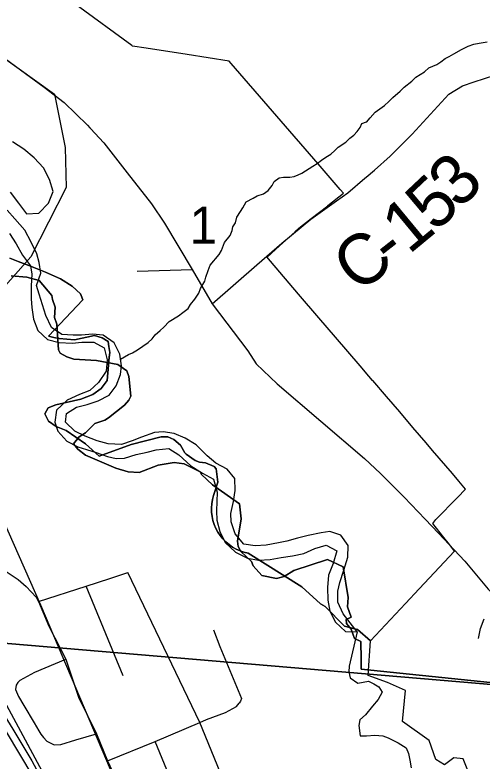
# Model space of a CAD drawing. Extents: x 0 to 43.4, y -8.1 to 22.
# Drawn here: x 3.073 to 3.6, y 17.64 to 18.481 of the extents above; entities that cross this region are included whole.
import ezdxf

# ---------------------------------------------------------------- set-up
doc = ezdxf.new("R2010")
doc.units = 0
for name, color, linetype in [('GM_X_City_Street', 7, 'Continuous'), ('GM_X_Corporation', 7, 'Continuous'), ('GM_X_County_Road', 7, 'Continuous'), ('GM_X_County_Road_Text', 7, 'Continuous'), ('GM_X_Minor_River', 7, 'Continuous'), ('GM_X_Rail_Line', 7, 'Continuous'), ('GM_X_Section_Text', 7, 'Continuous'), ('GM_X_US_Route', 7, 'Continuous')]:
    doc.layers.add(name, color=color, linetype=linetype)

msp = doc.modelspace()

# ---------------------------------------------------------------- linework, layer by layer
at = {"layer": 'GM_X_City_Street'}
for p, q in [((3.2111, 18.1925), (3.27309, 18.19442)), ((3.19527, 17.73658), (3.1535, 17.83752))]:
    msp.add_line(p, q, dxfattribs=at)
for points in [[(3.29588, 18.15593), (3.34631, 18.19974), (3.37441, 18.22416)], [(3.09997, 17.82012), (3.1535, 17.83752), (3.18049, 17.84629), (3.20062, 17.85284)], [(3.41245, 17.4317), (3.33759, 17.56832), (3.30496, 17.62788), (3.28186, 17.68384), (3.20062, 17.85284)], [(3.29742, 17.78848), (3.3046, 17.76964), (3.32903, 17.71089), (3.3279, 17.70799), (3.32629, 17.70557)], [(3.07918, 17.73165), (3.09576, 17.74051), (3.13053, 17.75532)], [(3.07918, 17.73165), (3.0766, 17.72892), (3.07468, 17.72585), (3.07387, 17.72119), (3.07741, 17.7133), (3.08337, 17.703), (3.09512, 17.68352), (3.10027, 17.6745), (3.10268, 17.6708), (3.10542, 17.66694), (3.10929, 17.66292), (3.1175, 17.65857), (3.12506, 17.65905), (3.14213, 17.6642), (3.1653, 17.67096)], [(3.17754, 17.6407), (3.23147, 17.66227), (3.28186, 17.68384), (3.28942, 17.68738), (3.31084, 17.69527), (3.32323, 17.70203), (3.32629, 17.70557)], [(3.28359, 17.55559), (3.25511, 17.60513), (3.23147, 17.66227)]]:
    msp.add_lwpolyline(points, dxfattribs=at)
at = {"layer": 'GM_X_Corporation'}
msp.add_lwpolyline([(3.83784, 18.69591), (3.74353, 17.71545), (2.85206, 17.7909), (2.81544, 17.7918), (2.81474, 17.79285), (2.79023, 17.83573), (2.76448, 17.88077), (2.76376, 17.88203), (2.74886, 17.90906), (2.84289, 18.81663)], close=True, dxfattribs=at)
for points in [[(3.06758, 18.20743), (3.07693, 18.20367), (3.08585, 18.20009), (3.08885, 18.19888), (3.10766, 18.19163), (3.12473, 18.1841), (3.13779, 18.17581), (3.14708, 18.16702), (3.14797, 18.16504), (3.15003, 18.16046), (3.11099, 18.11916), (3.11727, 18.11779), (3.12307, 18.11652), (3.14051, 18.11538), (3.16293, 18.12015), (3.17186, 18.11762), (3.17857, 18.11335), (3.1794, 18.10751), (3.18035, 18.10085), (3.17957, 18.09542), (3.17716, 18.06922), (3.17063, 18.06022), (3.1613, 18.05341), (3.14766, 18.04823), (3.11934, 18.04211), (3.11094, 18.03863), (3.10698, 18.03195), (3.11128, 18.02351), (3.11994, 18.01739), (3.13105, 18.01304), (3.15274, 17.99811), (3.16822, 17.98389), (3.20447, 17.99725), (3.23822, 18.00592), (3.24579, 18.006), (3.25264, 18.00275), (3.26013, 17.99636), (3.26484, 17.98771), (3.26655, 17.98646), (3.27663, 17.97912), (3.28137, 17.97721), (3.28816, 17.97654), (3.29793, 17.97241), (3.30041, 17.96981), (3.30223, 17.95476), (3.29894, 17.94425), (3.2973, 17.93978), (3.29609, 17.93517), (3.29532, 17.93048), (3.29498, 17.92573), (3.2951, 17.92097), (3.29566, 17.91624), (3.29666, 17.91159), (3.29809, 17.90705), (3.29994, 17.90266), (3.3022, 17.89847), (3.30484, 17.89451), (3.30783, 17.89081), (3.31116, 17.88741), (3.3148, 17.88434), (3.31871, 17.88162), (3.32285, 17.87928), (3.3272, 17.87734), (3.3317, 17.87581), (3.33634, 17.87471), (3.39686, 17.83685), (3.41783, 17.81755), (3.42314, 17.8147), (3.44525, 17.79256), (3.45971, 17.78878), (3.47424, 17.77575), (3.51403, 17.81814), (3.52923, 17.83466), (3.56914, 17.87704), (3.56336, 17.88461), (3.55725, 17.89236), (3.5449, 17.90802), (3.54823, 17.91256), (3.5724, 17.93737), (3.58173, 17.94695), (3.5742, 17.95576), (3.56676, 17.96445), (3.55935, 17.97313), (3.55192, 17.98181), (3.54448, 17.9905), (3.53705, 17.99918), (3.52964, 18.00786), (3.52221, 18.01654), (3.50734, 18.03392), (3.50005, 18.0427), (3.49257, 18.05135), (3.47687, 18.06927), (3.47674, 18.06942), (3.47266, 18.07418), (3.46275, 18.08575), (3.4488, 18.10202), (3.43487, 18.11829), (3.41628, 18.13998), (3.39336, 18.16673), (3.36155, 18.20385), (3.3613, 18.20414), (3.35779, 18.20827), (3.3718, 18.221), (3.38925, 18.237), (3.38939, 18.23714), (3.3937, 18.24109), (3.40764, 18.25188), (3.42637, 18.26637), (3.42629, 18.26647), (3.44394, 18.28045), (3.44032, 18.28463), (3.41525, 18.31356), (3.31714, 18.42677), (3.3149, 18.42934), (3.26749, 18.43679), (3.22135, 18.44395), (3.20606, 18.44634), (3.20519, 18.44698), (3.14232, 18.49279)], [(3.58813, 17.62035), (3.57888, 17.64276), (3.56845, 17.64403), (3.5579, 17.63601), (3.54803, 17.64217), (3.54041, 17.66358), (3.51061, 17.68514), (3.51402, 17.71999), (3.49376, 17.72903), (3.47188, 17.73679), (3.47424, 17.77575), (3.45971, 17.78878), (3.44525, 17.79256), (3.42314, 17.8147), (3.41783, 17.81755), (3.39686, 17.83685), (3.33634, 17.87471), (3.3317, 17.87581), (3.3272, 17.87734), (3.32285, 17.87928), (3.31871, 17.88162), (3.3148, 17.88434), (3.31116, 17.88741), (3.30783, 17.89081), (3.30484, 17.89451), (3.3022, 17.89847), (3.29994, 17.90266), (3.29809, 17.90705), (3.29666, 17.91159), (3.29566, 17.91624), (3.2951, 17.92097), (3.29498, 17.92573), (3.29532, 17.93048), (3.29609, 17.93517), (3.2973, 17.93978), (3.29894, 17.94425), (3.30223, 17.95476), (3.30041, 17.96981), (3.29793, 17.97241), (3.28816, 17.97654), (3.28137, 17.97721), (3.27663, 17.97912), (3.26655, 17.98646), (3.26484, 17.98771), (3.26013, 17.99636), (3.25264, 18.00275), (3.24579, 18.006), (3.23822, 18.00592), (3.20447, 17.99725), (3.16822, 17.98389), (3.15274, 17.99811), (3.13105, 18.01304), (3.11994, 18.01739), (3.11128, 18.02351), (3.10698, 18.03195), (3.11094, 18.03863), (3.11934, 18.04211), (3.14766, 18.04823), (3.1613, 18.05341), (3.17063, 18.06022), (3.17716, 18.06922), (3.17958, 18.0955), (3.18035, 18.10085), (3.1794, 18.10751), (3.17857, 18.11335), (3.17186, 18.11762), (3.16293, 18.12015), (3.14051, 18.11538), (3.12307, 18.11652), (3.11727, 18.11779), (3.11099, 18.11916), (3.15003, 18.16046), (3.14797, 18.16504), (3.14708, 18.16702), (3.13779, 18.17581), (3.12473, 18.1841), (3.10766, 18.19163), (3.08885, 18.19888), (3.08585, 18.20009), (3.07693, 18.20367), (3.06758, 18.20743)], [(3.06905, 18.1873), (3.08685, 18.18578), (3.10081, 18.18207), (3.11487, 18.16503), (3.11554, 18.16084), (3.11877, 18.15203), (3.11776, 18.14027), (3.12064, 18.13298), (3.1223, 18.10405), (3.1245, 18.10021), (3.13199, 18.09586), (3.13991, 18.09341), (3.1653, 18.09174), (3.18949, 18.08742), (3.19958, 18.08037), (3.20172, 18.07386), (3.20391, 18.05176), (3.20191, 18.04724), (3.19686, 18.04165), (3.17902, 18.02734), (3.17488, 18.02462), (3.16341, 18.02107), (3.15294, 18.01026), (3.14564, 18.00586), (3.1394, 17.998), (3.1442, 17.99182), (3.15279, 17.98518), (3.187, 17.97038), (3.20096, 17.96629), (3.21347, 17.96564), (3.23474, 17.97408), (3.25279, 17.97698), (3.26415, 17.97559), (3.28216, 17.96647), (3.28362, 17.9634), (3.29627, 17.95172), (3.32655, 17.93017), (3.32847, 17.9134), (3.32452, 17.88827), (3.32515, 17.8823), (3.32807, 17.87654), (3.34035, 17.86525), (3.34214, 17.86028), (3.35177, 17.84943), (3.3685, 17.84623), (3.37718, 17.84851), (3.38794, 17.85513), (3.42577, 17.86763), (3.44343, 17.85928), (3.44915, 17.82494), (3.44854, 17.81431), (3.45246, 17.80244), (3.4471, 17.79989), (3.44738, 17.79532), (3.45256, 17.78913), (3.45651, 17.7784), (3.46332, 17.77524), (3.46375, 17.75518), (3.46395, 17.7441), (3.74401, 17.71488)], [(3.74401, 17.71488), (3.46395, 17.7441), (3.46375, 17.75518), (3.46332, 17.77524), (3.45651, 17.7784), (3.45256, 17.78913), (3.44738, 17.79532), (3.4471, 17.79989), (3.45246, 17.80244), (3.44854, 17.81431), (3.44915, 17.82494), (3.44343, 17.85928), (3.42577, 17.86763), (3.38794, 17.85513), (3.37718, 17.84851), (3.3685, 17.84623), (3.35177, 17.84943), (3.34214, 17.86028), (3.34035, 17.86525), (3.32807, 17.87654), (3.32515, 17.8823), (3.32452, 17.88827), (3.32847, 17.9134), (3.32655, 17.93017), (3.29627, 17.95172), (3.28362, 17.9634), (3.28216, 17.96647), (3.26415, 17.97559), (3.25279, 17.97698), (3.23474, 17.97408), (3.21347, 17.96564), (3.20096, 17.96629), (3.187, 17.97038), (3.15279, 17.98518), (3.1442, 17.99182), (3.1394, 17.998), (3.14564, 18.00586), (3.15294, 18.01026), (3.16341, 18.02107), (3.17488, 18.02462), (3.17902, 18.02734), (3.19686, 18.04165), (3.20191, 18.04724), (3.20391, 18.05176), (3.20172, 18.07386), (3.19958, 18.08037), (3.18949, 18.08742), (3.1653, 18.09174), (3.13991, 18.09341), (3.13199, 18.09586), (3.1245, 18.10021), (3.1223, 18.10405), (3.12064, 18.13298), (3.11776, 18.14027), (3.11877, 18.15203), (3.11554, 18.16084), (3.11487, 18.16503), (3.10081, 18.18207), (3.08685, 18.18578), (3.06905, 18.1873)], [(2.85206, 17.7909), (3.74353, 17.71545), (3.64182, 16.58442)]]:
    msp.add_lwpolyline(points, dxfattribs=at)
at = {"layer": 'GM_X_County_Road'}
for points in [[(2.95255, 18.50867), (2.96704, 18.50011), (2.98234, 18.49058), (3.10627, 18.39992), (3.12896, 18.3826), (3.15521, 18.35722), (3.15795, 18.35427)], [(3.46955, 18.29869), (3.47875, 18.30652), (3.49664, 18.32239), (3.52124, 18.3472), (3.56269, 18.39209), (3.57813, 18.40156), (3.59154, 18.40615), (3.6147, 18.4136)], [(3.15795, 18.35427), (3.15863, 18.35354), (3.17366, 18.33735), (3.20007, 18.3036), (3.22721, 18.26869), (3.24217, 18.24664), (3.27309, 18.19442), (3.29588, 18.15593)], [(3.37441, 18.22416), (3.40702, 18.25104), (3.4361, 18.27194), (3.44884, 18.28109), (3.46801, 18.29739), (3.46955, 18.29869)], [(3.29588, 18.15593), (3.33592, 18.10278), (3.3453, 18.08804), (3.36921, 18.06563), (3.46768, 17.98156), (3.48571, 17.96465), (3.51251, 17.93796), (3.53596, 17.91315), (3.55103, 17.89722)], [(3.55103, 17.89722), (3.58067, 17.86588), (3.6073, 17.83426), (3.62973, 17.81303), (3.68972, 17.75444), (3.71562, 17.74251), (3.73925, 17.73062), (3.74182, 17.72958), (3.74562, 17.72803), (3.77665, 17.71545), (3.78254, 17.71305)], [(3.06354, 17.85396), (3.07696, 17.84519), (3.08592, 17.83718), (3.0971, 17.82515), (3.09997, 17.82012), (3.11151, 17.79249), (3.11197, 17.79158)], [(3.11197, 17.79158), (3.13053, 17.75532), (3.14495, 17.71238), (3.1653, 17.67096), (3.17754, 17.6407), (3.21773, 17.5553), (3.22747, 17.53271), (3.2411, 17.50978), (3.39163, 17.25657), (3.39949, 17.2491), (3.40842, 17.24132), (3.41436, 17.2355), (3.42396, 17.22391), (3.43737, 17.2005), (3.44031, 17.19537)]]:
    msp.add_lwpolyline(points, dxfattribs=at)
at = {"layer": 'GM_X_Minor_River'}
for points in [[(3.46985, 18.36067), (3.47419, 18.36546), (3.47973, 18.37173), (3.4848, 18.37574), (3.49024, 18.37935), (3.49495, 18.38375), (3.49967, 18.38853), (3.50788, 18.39547), (3.51221, 18.39988), (3.52118, 18.40679), (3.52551, 18.4112), (3.53521, 18.41733), (3.5403, 18.42171), (3.54916, 18.42559), (3.55382, 18.42847), (3.55851, 18.43249), (3.56314, 18.43461), (3.56855, 18.43746), (3.57708, 18.44249), (3.58442, 18.44604), (3.59096, 18.44848), (3.59707, 18.44978), (3.60585, 18.451)], [(3.19236, 18.09353), (3.2015, 18.09853), (3.20575, 18.10067), (3.21155, 18.10389), (3.22361, 18.11221), (3.22793, 18.11625), (3.2315, 18.12068), (3.23699, 18.12582), (3.24129, 18.12947), (3.2472, 18.13573), (3.25768, 18.14221), (3.26274, 18.14583), (3.2686, 18.15057), (3.27141, 18.15504), (3.27617, 18.16095), (3.28057, 18.16764), (3.28265, 18.17289), (3.28751, 18.18147), (3.2888, 18.18598), (3.29134, 18.1935), (3.29344, 18.19951), (3.30372, 18.21132), (3.30616, 18.21579), (3.30989, 18.22479), (3.31624, 18.23293), (3.31833, 18.23856), (3.31923, 18.24271), (3.32205, 18.24718), (3.32378, 18.25358), (3.3278, 18.2599), (3.33022, 18.264), (3.33425, 18.2707), (3.34199, 18.275), (3.34663, 18.2775), (3.35355, 18.27992), (3.35899, 18.28353), (3.36336, 18.28908), (3.36579, 18.29356), (3.37126, 18.29793), (3.37621, 18.29852), (3.38343, 18.29865), (3.38839, 18.29924), (3.39264, 18.30137), (3.39687, 18.30313), (3.40929, 18.31106), (3.41433, 18.31393), (3.41901, 18.31757), (3.42407, 18.3212), (3.4295, 18.32443), (3.43419, 18.32845), (3.43775, 18.33251), (3.44667, 18.3379), (3.45101, 18.34269), (3.45568, 18.34595), (3.45923, 18.35001), (3.4628, 18.35445), (3.46448, 18.35895), (3.46997, 18.3608)], [(3.06778, 18.28184), (3.07726, 18.26938), (3.08638, 18.25732), (3.10007, 18.25803), (3.11105, 18.26909), (3.11639, 18.28223), (3.11227, 18.29604), (3.10546, 18.30917), (3.0948, 18.32053), (3.08333, 18.33), (3.07067, 18.33838)], [(3.18514, 18.11173), (3.17287, 18.12047), (3.16076, 18.12161), (3.14857, 18.12046), (3.13907, 18.12038), (3.12619, 18.12116), (3.11467, 18.12912), (3.10825, 18.14262), (3.10444, 18.15452), (3.10065, 18.1668), (3.09753, 18.1764), (3.10252, 18.1903), (3.10062, 18.20252), (3.09788, 18.21211), (3.09146, 18.22523), (3.08428, 18.23876), (3.07329, 18.25164), (3.06448, 18.26142)], [(3.06708, 18.23511), (3.07469, 18.22347), (3.08189, 18.21071), (3.09101, 18.19864), (3.09223, 18.1891), (3.09145, 18.17621), (3.09175, 18.16137), (3.0922, 18.15148), (3.09407, 18.1385), (3.09899, 18.1258), (3.11007, 18.11558), (3.12325, 18.11213), (3.13803, 18.11129), (3.1487, 18.11248), (3.16237, 18.11244), (3.17394, 18.106), (3.17732, 18.09259), (3.17616, 18.0797), (3.16741, 18.06705), (3.15764, 18.05823), (3.14611, 18.05365), (3.13224, 18.04724), (3.12011, 18.03583), (3.11817, 18.02221), (3.12166, 18.01222), (3.13194, 18.00088), (3.14427, 17.99442), (3.15405, 17.99145), (3.16495, 17.98807), (3.17774, 17.98388), (3.18753, 17.9813), (3.19703, 17.98176), (3.21008, 17.98592), (3.22231, 17.98858), (3.23265, 17.9913), (3.24674, 17.99276), (3.25829, 17.98557), (3.27157, 17.97299), (3.28499, 17.96497)], [(3.45941, 17.78589), (3.44372, 17.80651), (3.43767, 17.81962), (3.43767, 17.83178), (3.43988, 17.8416), (3.44449, 17.85552), (3.44874, 17.87021), (3.44916, 17.8835), (3.44078, 17.89516), (3.42838, 17.89934), (3.41884, 17.89774), (3.40394, 17.89478), (3.39207, 17.89173), (3.38019, 17.88829), (3.37064, 17.88631), (3.35689, 17.8837), (3.34433, 17.88294), (3.33148, 17.88486), (3.32159, 17.89657), (3.31707, 17.91001), (3.31699, 17.91952), (3.31969, 17.93311), (3.32159, 17.94522), (3.32126, 17.95891), (3.31285, 17.96943), (3.29977, 17.9763), (3.29016, 17.98458), (3.27763, 17.99675), (3.26533, 18.00435), (3.25297, 18.00967), (3.24049, 18.01158), (3.23059, 18.01075), (3.216, 18.0055), (3.20562, 18.00126), (3.19334, 17.99708), (3.17855, 17.99792), (3.16613, 18.00134), (3.15262, 18.0067), (3.14103, 18.01238), (3.13032, 18.02221), (3.13139, 18.03206), (3.14263, 18.03932), (3.15487, 18.04236), (3.16715, 18.04654), (3.17951, 18.053), (3.18743, 18.06339), (3.19238, 18.07616), (3.19345, 18.08601), (3.19157, 18.09899), (3.18514, 18.11173)], [(3.28499, 17.96497), (3.29731, 17.95813), (3.30141, 17.94356), (3.30075, 17.9223), (3.30119, 17.91202), (3.30458, 17.899), (3.31027, 17.88666), (3.32209, 17.87603), (3.33555, 17.86915), (3.34801, 17.86687), (3.36132, 17.8676), (3.37354, 17.86988), (3.38652, 17.87175), (3.39913, 17.8744), (3.41146, 17.88011), (3.42449, 17.88388), (3.43643, 17.87743), (3.43219, 17.86312), (3.42685, 17.84998), (3.42603, 17.83595), (3.42635, 17.82187), (3.42862, 17.80926), (3.43507, 17.7969), (3.44613, 17.7863), (3.45941, 17.78589)], [(3.59628, 17.77854), (3.59857, 17.78986), (3.60274, 17.80074)], [(3.45941, 17.78589), (3.45034, 17.7474), (3.44984, 17.74095), (3.45163, 17.73407), (3.4603, 17.72822), (3.47218, 17.73029), (3.47824, 17.72752), (3.4839, 17.724), (3.48761, 17.71823), (3.48288, 17.70995), (3.47663, 17.70208), (3.46881, 17.69234), (3.46222, 17.68675), (3.46134, 17.6803), (3.46266, 17.66888), (3.46991, 17.66875), (3.47947, 17.66972), (3.48824, 17.6688), (3.49431, 17.66642), (3.50566, 17.66089), (3.51473, 17.65541), (3.51728, 17.6489), (3.51867, 17.64128), (3.52042, 17.63288)]]:
    msp.add_lwpolyline(points, dxfattribs=at)
at = {"layer": 'GM_X_Rail_Line'}
for points in [[(2.1, 18.9805), (2.18479, 18.94971), (2.35922, 18.83828), (2.50145, 18.75122), (2.6158, 18.69068), (2.7269, 18.63112), (2.78928, 18.6123), (2.86626, 18.5659), (2.96588, 18.50136), (3.05814, 18.43481), (3.11797, 18.39209), (3.12988, 18.33213), (3.13125, 18.28696), (3.09119, 18.20871), (3.02799, 18.13775), (3.0132, 18.08565), (3.01376, 18.04304), (3.01544, 18.01215), (3.10201, 17.81662), (3.20062, 17.58444), (3.39519, 17.25691), (3.42056, 17.22879), (3.49934, 17.0909)], [(2.45327, 18.5052), (2.62977, 18.32207), (2.6528, 18.29733), (2.6725, 18.27411), (2.68331, 18.25906), (2.6949, 18.24319), (2.71067, 18.22229), (2.74112, 18.18099), (2.83449, 18.04911), (2.88788, 17.97338), (2.91038, 17.94007), (2.93069, 17.90856), (2.95907, 17.86111), (3.00629, 17.78076), (3.07095, 17.67632), (3.09239, 17.64061), (3.11703, 17.59454), (3.17827, 17.49059), (3.21708, 17.42507), (3.25801, 17.35521), (3.31559, 17.2606), (3.348, 17.20781), (3.39098, 17.1363)], [(3.06329, 17.67327), (3.18142, 17.47556), (3.22865, 17.39537), (3.2625, 17.33617), (3.28933, 17.29051), (3.32553, 17.22935), (3.35356, 17.18683), (3.38378, 17.13646)]]:
    msp.add_lwpolyline(points, dxfattribs=at)
at = {"layer": 'GM_X_US_Route'}
msp.add_lwpolyline([(2.82333, 18.24556), (2.82607, 18.23616), (2.82847, 18.22673), (2.83109, 18.21643), (2.85243, 18.13263), (2.8706, 18.06727), (2.89038, 18.02162), (2.91824, 17.96516), (2.95315, 17.90245), (2.97474, 17.86967), (3.02474, 17.78762), (3.05536, 17.71815), (3.11934, 17.60024), (3.19152, 17.4797), (3.253, 17.37367), (3.34917, 17.21409), (3.46662, 17.02243)], dxfattribs=at)

# ---------------------------------------------------------------- texts
at = {"layer": 'GM_X_County_Road_Text'}
for s, rotation, p in [('3', 45.41607, (3.57465, 18.26122)), ('5', 43.33389, (3.54758, 18.23563)), ('1', 39.58844, (3.51757, 18.21064)), ('C', 37.65128, (3.46059, 18.16645)), ('-', 38.00337, (3.49784, 18.19519))]:
    msp.add_text(s, height=0.05682, rotation=rotation, dxfattribs=at).set_placement(p)
at = {"layer": 'GM_X_Section_Text'}
msp.add_text('1', height=0.04186, rotation=0.00001, dxfattribs=at).set_placement((3.27018, 18.22356))

doc.saveas('drawing.dxf')
